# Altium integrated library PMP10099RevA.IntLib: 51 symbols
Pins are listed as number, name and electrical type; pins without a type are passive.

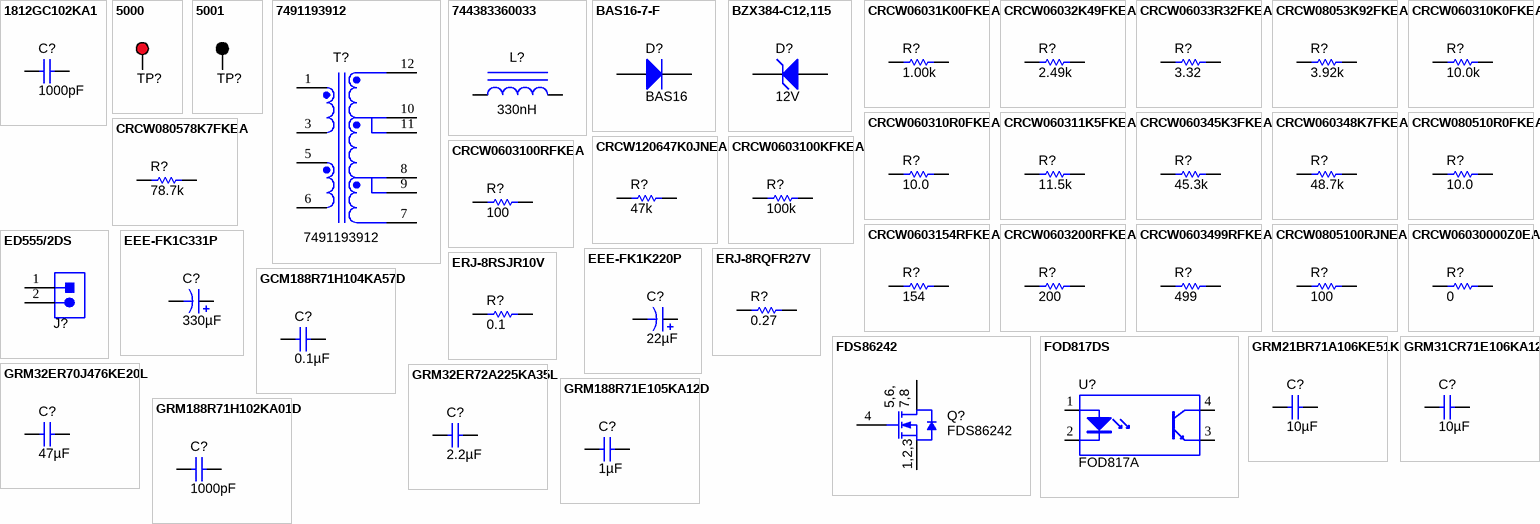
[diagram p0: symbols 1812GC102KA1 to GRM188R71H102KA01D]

## 1812GC102KA1
designator C?  ValueDisplayed: 1000pF  (hidden comment: 1812GC102KA1)
CAP, CERM, 1000 pF, 2000 V, +/- 10%, X7R, 1812; Manufacturer: AVX; Polarized: N; CompType: Capacitor; Value: 1000pF; U/M: EA; Cap_F: 0.000000001; Tolerance_%: 10; Value1: Unknown; VDC_V: 2000; Value2: 2000V; TaMin_C: -55; TaMax_C: 125; Cap_Case: 1812
signal-integrity model Cap
simulation model Cap
footprint 1812
footprint 1812M
footprint 1812L
footprint 1812_HV
pins: 1, 2

## 5000
designator TP?  (value not drawn)
Test Point, Miniature, Red, TH; Manufacturer: Keystone; CompType: Test Point Loop; U/M: EA
footprint Keystone5000
pins: 1

## 5001
designator TP?  (value not drawn)
Test Point, Miniature, Black, TH; Manufacturer: Keystone; CompType: Test Point Loop; U/M: EA
footprint Keystone5001
pins: 1

## 7491193912
designator T?
Transformer, 120 uH, SMT; Manufacturer: Wurth Elektronik eiSos; SymbolCreator: Altium; DCR_Ohm: 0.22; Value: 120 uH; LeakageL: 1.5 uH; U/M: EA
footprint WURTH_7491193912
pins: 1, 3, 5, 6, 7, 8, 9, 10, 11, 12

## 744383360033
designator L?, comment 330nH
Inductor, 330 nH, 5.5 A, 0.014 ohm, SMD; PartNumber: 744383360033; Manufacturer: Wurth Elektronik eiSos; Ind_H: 330.0E-9; Imax_A: 5.5; Irms: 5.5A @ 40C rise; Isat: 8.3A @ 20% inductance drop; DCR_ohm: 0.014; Value2: 5.5A
signal-integrity model Inductor
simulation model Inductor
footprint WE-MAPI_3020
pins: 1, 2

## BAS16-7-F
designator D?, comment BAS16
Diode, Ultrafast, 75 V, 0.3 A, SOT-23; PartNumber: BAS16-7-F; Manufacturer: Diodes Inc.; U/M: EA; Vf_V: 1.125; Value: 75V; Value1: 0.3A; Value2: 1.125V; Io_A: 0.3; Vr_V: 75
signal-integrity model Model Name (Model Description)
simulation model DI_MMBD4148
footprint SOT-23
footprint SOT-23M
footprint SOT-23L
pins: 1 A, 3 K

## BZX384-C12,115
designator D?  value 12V  (hidden comment: BZX384-C12,115)
Diode, Zener, 12 V, 300 mW, SOD-323; Manufacturer: NXP Semiconductor; SymbolCreator: a0412235; U/M: EA; Power_W: 0.3; Vz_V: 12; Value1: 0.3W; RJA_CperW: 415
signal-integrity model Diode
footprint sod-323
pins: 1 K, 2 A

## CRCW06031K00FKEA
designator R?  ValueDisplayed: 1.00k  (hidden comment: CRCW06031K00FKEA)
RES, 1.00 k, 1%, 0.1 W, 0603; Manufacturer: Vishay-Dale; CompType: Resistor; Value: 1.00k; Res_ohm: 1000; Value_Code: 1k00; Tolerance_%: 1; Power_W: 0.1; Value2: 0.1W; VDC_V: 75; TempCo: 100 ppm/C; EIA_Code: E96; U/M: EA
signal-integrity model Resistor
simulation model Resistor
footprint 0603
footprint 0603M
footprint 0603L
footprint 0603_HV
footprint 0603S
pins: 1, 2

## CRCW06032K49FKEA
designator R?  ValueDisplayed: 2.49k  (hidden comment: CRCW06032K49FKEA)
RES, 2.49 k, 1%, 0.1 W, 0603; Manufacturer: Vishay-Dale; CompType: Resistor; Value: 2.49k; Res_ohm: 2490; Value_Code: 2k49; Tolerance_%: 1; Power_W: 0.1; Value2: 0.1W; VDC_V: 75; TempCo: 100 ppm/C; EIA_Code: E96; U/M: EA
signal-integrity model Resistor
simulation model Resistor
footprint 0603
footprint 0603M
footprint 0603L
footprint 0603_HV
footprint 0603S
pins: 1, 2

## CRCW06033R32FKEA
designator R?  ValueDisplayed: 3.32  (hidden comment: CRCW06033R32FKEA)
RES, 3.32, 1%, 0.1 W, 0603; Manufacturer: Vishay-Dale; CompType: Resistor; Value: 3.32; Value_Code: 3R32; Tolerance_%: 1; Power_W: 0.1; Value2: 0.1W; VDC_V: 75; TempCo: 100 ppm/C; EIA_Code: E96; U/M: EA
signal-integrity model Resistor
simulation model Resistor
footprint 0603
footprint 0603M
footprint 0603L
footprint 0603_HV
footprint 0603S
pins: 1, 2

## CRCW08053K92FKEA
designator R?  value 3.92k  (hidden comment: CRCW08053K92FKEA)
RES, 3.92k ohm, 1%, 0.125W, 0805; Manufacturer: Vishay-Dale; CompType: Resistor; Res_ohm: 3920; Value_Code: 3k92; Tolerance_%: 1; Power_W: 0.125; VDC_V: 150; TempCo: 100 ppm/C; EIA_Code: E96; U/M: EA
signal-integrity model Resistor
simulation model Resistor
footprint 0805_HV
footprint 0805
footprint 0805M
footprint 0805L
pins: 1, 2

## CRCW060310K0FKEA
designator R?  ValueDisplayed: 10.0k  (hidden comment: CRCW060310K0FKEA)
RES, 10.0 k, 1%, 0.1 W, 0603; Manufacturer: Vishay-Dale; CompType: Resistor; Value: 10.0k; Res_ohm: 10000; Value_Code: 10k0; Tolerance_%: 1; Power_W: 0.1; Value2: 0.1W; VDC_V: 75; TempCo: 100 ppm/C; EIA_Code: E96; U/M: EA
signal-integrity model Resistor
simulation model Resistor
footprint 0603
footprint 0603M
footprint 0603L
footprint 0603_HV
footprint 0603S
pins: 1, 2

## CRCW060310R0FKEA
designator R?  ValueDisplayed: 10.0  (hidden comment: CRCW060310R0FKEA)
RES, 10.0, 1%, 0.1 W, 0603; Manufacturer: Vishay-Dale; CompType: Resistor; Value: 10.0; Res_ohm: 10; Value_Code: 10R0; Tolerance_%: 1; Power_W: 0.1; Value2: 0.1W; VDC_V: 75; TempCo: 100 ppm/C; EIA_Code: E96; U/M: EA
signal-integrity model Resistor
simulation model Resistor
footprint 0603
footprint 0603M
footprint 0603L
footprint 0603_HV
footprint 0603S
pins: 1, 2

## CRCW060311K5FKEA
designator R?  ValueDisplayed: 11.5k  (hidden comment: CRCW060311K5FKEA)
RES, 11.5 k, 1%, 0.1 W, 0603; Manufacturer: Vishay-Dale; CompType: Resistor; Value: 11.5k; Res_ohm: 11500; Value_Code: 11k5; Tolerance_%: 1; Power_W: 0.1; Value2: 0.1W; VDC_V: 75; TempCo: 100 ppm/C; EIA_Code: E96; U/M: EA
signal-integrity model Resistor
simulation model Resistor
footprint 0603
footprint 0603M
footprint 0603L
footprint 0603_HV
footprint 0603S
pins: 1, 2

## CRCW060345K3FKEA
designator R?  ValueDisplayed: 45.3k  (hidden comment: CRCW060345K3FKEA)
RES, 45.3 k, 1%, 0.1 W, 0603; Manufacturer: Vishay-Dale; CompType: Resistor; Value: 45.3k; Res_ohm: 45300; Value_Code: 45k3; Tolerance_%: 1; Power_W: 0.1; Value2: 0.1W; VDC_V: 75; TempCo: 100 ppm/C; EIA_Code: E96; U/M: EA
signal-integrity model Resistor
simulation model Resistor
footprint 0603
footprint 0603M
footprint 0603L
footprint 0603_HV
footprint 0603S
pins: 1, 2

## CRCW060348K7FKEA
designator R?  ValueDisplayed: 48.7k  (hidden comment: CRCW060348K7FKEA)
RES, 48.7 k, 1%, 0.1 W, 0603; Manufacturer: Vishay-Dale; CompType: Resistor; Value: 48.7k; Res_ohm: 48700; Value_Code: 48k7; Tolerance_%: 1; Power_W: 0.1; Value2: 0.1W; VDC_V: 75; TempCo: 100 ppm/C; EIA_Code: E96; U/M: EA
signal-integrity model Resistor
simulation model Resistor
footprint 0603
footprint 0603M
footprint 0603L
footprint 0603_HV
footprint 0603S
pins: 1, 2

## CRCW080510R0FKEA
designator R?  value 10.0  (hidden comment: CRCW080510R0FKEA)
RES, 10.0 ohm, 1%, 0.125W, 0805; Manufacturer: Vishay-Dale; CompType: Resistor; Res_ohm: 10; Value_Code: 10R0; Tolerance_%: 1; Power_W: 0.125; VDC_V: 150; TempCo: 100 ppm/C; EIA_Code: E96; U/M: EA
signal-integrity model Resistor
simulation model Resistor
footprint 0805_HV
footprint 0805
footprint 0805M
footprint 0805L
pins: 1, 2

## CRCW080578K7FKEA
designator R?  value 78.7k  (hidden comment: CRCW080578K7FKEA)
RES, 78.7k ohm, 1%, 0.125W, 0805; Manufacturer: Vishay-Dale; CompType: Resistor; Res_ohm: 78700; Value_Code: 78k7; Tolerance_%: 1; Power_W: 0.125; VDC_V: 150; TempCo: 100 ppm/C; EIA_Code: E96; U/M: EA
signal-integrity model Resistor
simulation model Resistor
footprint 0805_HV
footprint 0805
footprint 0805M
footprint 0805L
pins: 1, 2

## CRCW120647K0JNEA
designator R?  ValueDisplayed: 47k  (hidden comment: CRCW120647K0JNEA)
RES, 47 k, 5%, 0.25 W, 1206; Manufacturer: Vishay-Dale; CompType: Resistor; Value: 47k; Res_ohm: 47000; Value_Code: 47k0; Tolerance_%: 5; Power_W: 0.25; Value2: 0.25W; VDC_V: 200; TempCo: 200 ppm/C; EIA_Code: E24; U/M: EA
signal-integrity model Resistor
simulation model Resistor
footprint 1206
footprint 1206M
footprint 1206L
pins: 1, 2

## CRCW0603100KFKEA
designator R?  ValueDisplayed: 100k  (hidden comment: CRCW0603100KFKEA)
RES, 100 k, 1%, 0.1 W, 0603; Manufacturer: Vishay-Dale; CompType: Resistor; Value: 100k; Res_ohm: 100000; Tolerance_%: 1; Power_W: 0.1; Value2: 0.1W; VDC_V: 75; TempCo: 100 ppm/C; EIA_Code: E96; U/M: EA
signal-integrity model Resistor
simulation model Resistor
footprint 0603
footprint 0603M
footprint 0603L
footprint 0603_HV
footprint 0603S
pins: 1, 2

## CRCW0603100RFKEA
designator R?  ValueDisplayed: 100  (hidden comment: CRCW0603100RFKEA)
RES, 100, 1%, 0.1 W, 0603; Manufacturer: Vishay-Dale; CompType: Resistor; Value: 100; Value_Code: 100R; Tolerance_%: 1; Power_W: 0.1; Value2: 0.1W; VDC_V: 75; TempCo: 100 ppm/C; EIA_Code: E96; U/M: EA
signal-integrity model Resistor
simulation model Resistor
footprint 0603
footprint 0603M
footprint 0603L
footprint 0603_HV
footprint 0603S
pins: 1, 2

## CRCW0603154RFKEA
designator R?  ValueDisplayed: 154  (hidden comment: CRCW0603154RFKEA)
RES, 154, 1%, 0.1 W, 0603; Manufacturer: Vishay-Dale; CompType: Resistor; Value: 154; Value_Code: 154R; Tolerance_%: 1; Power_W: 0.1; Value2: 0.1W; VDC_V: 75; TempCo: 100 ppm/C; EIA_Code: E96; U/M: EA
signal-integrity model Resistor
simulation model Resistor
footprint 0603
footprint 0603M
footprint 0603L
footprint 0603_HV
footprint 0603S
pins: 1, 2

## CRCW0603200RFKEA
designator R?  ValueDisplayed: 200  (hidden comment: CRCW0603200RFKEA)
RES, 200, 1%, 0.1 W, 0603; Manufacturer: Vishay-Dale; CompType: Resistor; Value: 200; Value_Code: 200R; Tolerance_%: 1; Power_W: 0.1; Value2: 0.1W; VDC_V: 75; TempCo: 100 ppm/C; EIA_Code: E96; U/M: EA
signal-integrity model Resistor
simulation model Resistor
footprint 0603
footprint 0603M
footprint 0603L
footprint 0603_HV
footprint 0603S
pins: 1, 2

## CRCW0603499RFKEA
designator R?  ValueDisplayed: 499  (hidden comment: CRCW0603499RFKEA)
RES, 499, 1%, 0.1 W, 0603; Manufacturer: Vishay-Dale; CompType: Resistor; Value: 499; Value_Code: 499R; Tolerance_%: 1; Power_W: 0.1; Value2: 0.1W; VDC_V: 75; TempCo: 100 ppm/C; EIA_Code: E96; U/M: EA
signal-integrity model Resistor
simulation model Resistor
footprint 0603
footprint 0603M
footprint 0603L
footprint 0603_HV
footprint 0603S
pins: 1, 2

## CRCW0805100RJNEA
designator R?  value 100  (hidden comment: CRCW0805100RJNEA)
RES, 100 ohm, 5%, 0.125W, 0805; Manufacturer: Vishay-Dale; CompType: Resistor; Value_Code: 100R; Tolerance_%: 5; Power_W: 0.125; VDC_V: 150; TempCo: 200 ppm/C; EIA_Code: E24; U/M: EA
signal-integrity model Resistor
simulation model Resistor
footprint 0805_HV
footprint 0805
footprint 0805M
footprint 0805L
pins: 1, 2

## CRCW06030000Z0EA
designator R?  ValueDisplayed: 0  (hidden comment: CRCW06030000Z0EA)
RES, 0, 5%, 0.1 W, 0603; Manufacturer: Vishay-Dale; CompType: Resistor; Value: 0; Value_Code: 0000; Tolerance_%: 5; Power_W: 0.1; Value2: 0.1W; VDC_V: 75; TempCo: 200 ppm/C; EIA_Code: E24; U/M: EA
signal-integrity model Resistor
simulation model Resistor
footprint 0603
footprint 0603M
footprint 0603L
footprint 0603_HV
footprint 0603S
pins: 1, 2

## ED555/2DS
designator J?  (value not drawn)
Terminal Block, 6A, 3.5mm Pitch, 2-Pos, TH; Manufacturer: On-Shore Technology; SymbolCreator: a0412235; CompType: Connector; U/M: EA
footprint TERM_BLK_ED555-2DS
pins: 1, 2
1 alternate drawing of the same symbol

## EEE-FK1C331P
designator C?  ValueDisplayed: 330µF  (hidden comment: EEE-FK1C331P)
CAP, AL, 330 µF, 16 V, +/- 20%, 0.16 ohm, SMD; Manufacturer: Panasonic; Polarized: Y; CompType: Capacitor; Value: 330uF; U/M: EA; Cap_F: 0.00033; Tolerance_%: 20; VDC_V: 16; Value2: 16V; ESR_ohm: 0.16; IRMS_A: 0.6; TaMin_C: -55; TaMax_C: 105; Cap_Case: F
signal-integrity model Cap
simulation model Cap
footprint SM_RADIAL_F
pins: 1 +, 2 -

## EEE-FK1K220P
designator C?  ValueDisplayed: 22µF  (hidden comment: EEE-FK1K220P)
CAP, AL, 22 µF, 80 V, +/- 20%, 1.3 ohm, SMD; Manufacturer: Panasonic; Polarized: Y; CompType: Capacitor; Value: 22uF; U/M: EA; Cap_F: 0.000022; Tolerance_%: 20; Value1: 1.3 ohm; VDC_V: 80; Value2: 80V; ESR_ohm: 1.3; IRMS_A: 0.13; TaMin_C: -55; TaMax_C: 105; Cap_Case: F
signal-integrity model Cap
simulation model Cap
footprint SM_RADIAL_F
pins: 1 +, 2 -

## ERJ-8RQFR27V
designator R?  ValueDisplayed: 0.27  (hidden comment: ERJ-8RQFR27V)
RES, 0.27, 1%, 0.25 W, 1206; Manufacturer: Panasonic; CompType: Resistor; Value: 0.27; Value_Code: R270; Tolerance_%: 1; Power_W: 0.25; Value2: 0.25W; TempCo: 250 ppm/C; EIA_Code: E96; U/M: EA
signal-integrity model Resistor
simulation model Resistor
footprint 1206
footprint 1206M
footprint 1206L
pins: 1, 2

## ERJ-8RSJR10V
designator R?  ValueDisplayed: 0.1  (hidden comment: ERJ-8RSJR10V)
RES, 0.1, 5%, 0.25 W, 1206; Manufacturer: Panasonic; CompType: Resistor; Value: 0.1; Value_Code: R100; Tolerance_%: 5; Power_W: 0.25; Value2: 0.25W; TempCo: 250 ppm/C; EIA_Code: E24; U/M: EA
signal-integrity model Resistor
simulation model Resistor
footprint 1206
footprint 1206M
footprint 1206L
pins: 1, 2

## FDS86242
designator Q?
MOSFET, N-CH, 150 V, 4.1 A, SOIC-8; Manufacturer: Fairchild Semiconductor; Alternate Manufacturer: None; U/M: EA; ChType: N; Value: 150V; VdsMax_V: 150; Value1: 0.067 ohm; Rdson45_ohm: 0.067; Value2: 13 nC; QgTyp_nC: 13; Vgs_V: 4; IdsMax_A: 4.1
footprint SOIC-8
footprint SOIC-8M
footprint SOIC-8L
pins: 1 S, 2 S, 3 S, 4 G, 5 D, 6 D, 7 D, 8 D

## FOD817DS
designator U?, comment FOD817A
Optocoupler, 5kV RMS, SMT; PartNumber: FOD817DS; Manufacturer: Fairchild Semiconductor; U/M: EA
footprint N04C
pins: 1 A, 2 K, 3 E, 4 C

## GCM188R71H104KA57D
designator C?  ValueDisplayed: 0.1µF  (hidden comment: GCM188R71H104KA57D)
CAP, CERM, 0.1 µF, 50 V, +/- 10%, X7R, 0603; Manufacturer: MuRata; Polarized: N; CompType: Capacitor; Value: 0.1uF; U/M: EA; Cap_F: 0.0000001; Tolerance_%: 10; ESR_ohm: 0.02; Value1: 0.02 ohm; VDC_V: 50; Value2: 50V; IRMS_A: 1.84; TaMin_C: -55; TaMax_C: 125; Cap_Case: 0603
signal-integrity model Cap
simulation model Cap
footprint 0603
footprint 0603M
footprint 0603L
footprint 0603_HV
footprint 0603S
pins: 1, 2

## GRM21BR71A106KE51K
designator C?  ValueDisplayed: 10µF  (hidden comment: GRM21BR71A106KE51K)
CAP, CERM, 10 µF, 10 V, +/- 10%, X7R, 0805_140; Manufacturer: MuRata; Polarized: N; CompType: Capacitor; Value: 10uF; U/M: EA; Cap_F: 0.00001; Tolerance_%: 10; Value1: Unknown; Value2: 10V; TaMin_C: -55; TaMax_C: 125; Cap_Case: 0805
signal-integrity model Cap
simulation model Cap
footprint 0805_140
pins: 1, 2

## GRM31CR71E106KA12L
designator C?  ValueDisplayed: 10µF  (hidden comment: GRM31CR71E106KA12L)
CAP, CERM, 10 µF, 25 V, +/- 10%, X7R, 1206; Manufacturer: MuRata; Polarized: N; CompType: Capacitor; Value: 10uF; U/M: EA; Cap_F: 0.00001; Tolerance_%: 10; Value1: Unknown; VDC_V: 25; Value2: 25V; TaMin_C: -55; TaMax_C: 125; Cap_Case: 2220
signal-integrity model Cap
simulation model Cap
footprint 1206
footprint 1206M
footprint 1206L
pins: 1, 2

## GRM32ER70J476KE20L
designator C?  ValueDisplayed: 47µF  (hidden comment: GRM32ER70J476KE20L)
CAP, CERM, 47 µF, 6.3 V, +/- 10%, X7R, 1210; Manufacturer: MuRata; Polarized: N; CompType: Capacitor; Value: 47uF; U/M: EA; Cap_F: 0.000047; Tolerance_%: 10; Value1: Unknown; VDC_V: 6.3; Value2: 6.3V; TaMin_C: -55; TaMax_C: 125; Cap_Case: 1210
signal-integrity model Cap
simulation model Cap
footprint 1210
footprint 1210M
footprint 1210L
pins: 1, 2

## GRM32ER72A225KA35L
designator C?  ValueDisplayed: 2.2µF  (hidden comment: GRM32ER72A225KA35L)
CAP, CERM, 2.2 µF, 100 V, +/- 10%, X7R, 1210; Manufacturer: MuRata; Polarized: N; CompType: Capacitor; Value: 2.2uF; U/M: EA; Cap_F: 0.0000022; Tolerance_%: 10; ESR_ohm: 0.007; Value1: 0.007 ohm; VDC_V: 100; Value2: 100V; IRMS_A: 4.4; TaMin_C: -55; TaMax_C: 125; Cap_Case: 1210
signal-integrity model Cap
simulation model Cap
footprint 1210
footprint 1210M
footprint 1210L
pins: 1, 2

## GRM188R71E105KA12D
designator C?  ValueDisplayed: 1µF  (hidden comment: GRM188R71E105KA12D)
CAP, CERM, 1 µF, 25 V, +/- 10%, X7R, 0603; Manufacturer: MuRata; Polarized: N; CompType: Capacitor; Value: 1uF; U/M: EA; Cap_F: 0.000001; Tolerance_%: 10; Value1: Unknown; VDC_V: 25; Value2: 25V; TaMin_C: -55; TaMax_C: 125; Cap_Case: 0603
signal-integrity model Cap
simulation model Cap
footprint 0603
footprint 0603M
footprint 0603L
footprint 0603_HV
footprint 0603S
pins: 1, 2

## GRM188R71H102KA01D
designator C?  ValueDisplayed: 1000pF  (hidden comment: GRM188R71H102KA01D)
CAP, CERM, 1000 pF, 50 V, +/- 10%, X7R, 0603; Manufacturer: MuRata; Polarized: N; CompType: Capacitor; Value: 1000pF; U/M: EA; Cap_F: 0.000000001; Tolerance_%: 10; Value1: Unknown; VDC_V: 50; Value2: 50V; TaMin_C: -55; TaMax_C: 125; Cap_Case: 0603
signal-integrity model Cap
simulation model Cap
footprint 0603
footprint 0603M
footprint 0603L
footprint 0603_HV
footprint 0603S
pins: 1, 2

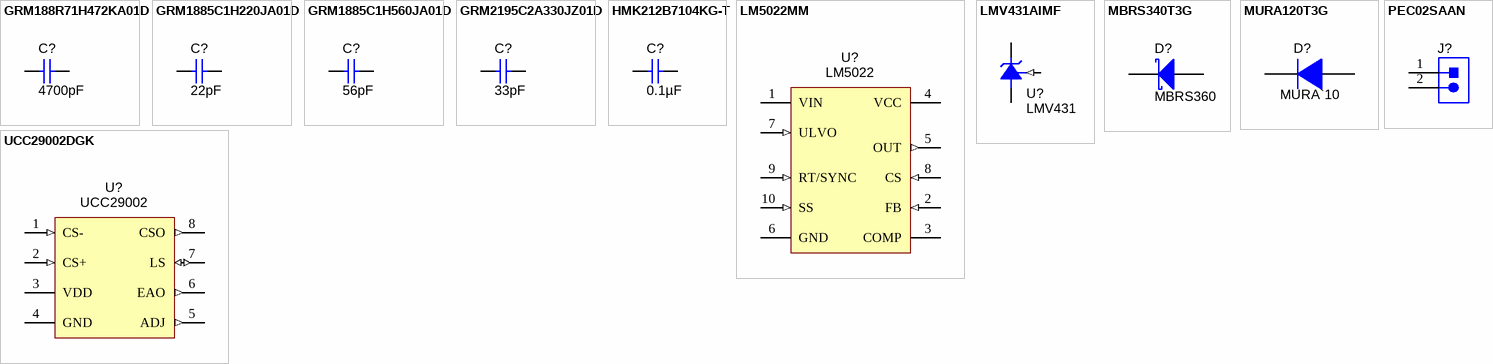
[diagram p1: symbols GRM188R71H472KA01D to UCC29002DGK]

## GRM188R71H472KA01D
designator C?  ValueDisplayed: 4700pF  (hidden comment: GRM188R71H472KA01D)
CAP, CERM, 4700 pF, 50 V, +/- 10%, X7R, 0603; Manufacturer: MuRata; Polarized: N; CompType: Capacitor; Value: 4700pF; U/M: EA; Cap_F: 0.0000000047; Tolerance_%: 10; Value1: Unknown; VDC_V: 50; Value2: 50V; TaMin_C: -55; TaMax_C: 125; Cap_Case: 0603
signal-integrity model Cap
simulation model Cap
footprint 0603
footprint 0603M
footprint 0603L
footprint 0603_HV
footprint 0603S
pins: 1, 2

## GRM1885C1H220JA01D
designator C?  ValueDisplayed: 22pF  (hidden comment: GRM1885C1H220JA01D)
CAP, CERM, 22 pF, 50 V, +/- 5%, C0G/NP0, 0603; Manufacturer: MuRata; Polarized: N; CompType: Capacitor; Value: 22pF; U/M: EA; Cap_F: 0.000000000022; Tolerance_%: 5; Value1: Unknown; VDC_V: 50; Value2: 50V; TaMin_C: -55; TaMax_C: 125; Cap_Case: 0603
signal-integrity model Cap
simulation model Cap
footprint 0603
footprint 0603M
footprint 0603L
footprint 0603_HV
footprint 0603S
pins: 1, 2

## GRM1885C1H560JA01D
designator C?  ValueDisplayed: 56pF  (hidden comment: GRM1885C1H560JA01D)
CAP, CERM, 56 pF, 50 V, +/- 5%, C0G/NP0, 0603; Manufacturer: MuRata; Polarized: N; CompType: Capacitor; Value: 56pF; U/M: EA; Cap_F: 0.000000000056; Tolerance_%: 5; Value1: Unknown; VDC_V: 50; Value2: 50V; TaMin_C: -55; TaMax_C: 125; Cap_Case: 0603
signal-integrity model Cap
simulation model Cap
footprint 0603
footprint 0603M
footprint 0603L
footprint 0603_HV
footprint 0603S
pins: 1, 2

## GRM2195C2A330JZ01D
designator C?  ValueDisplayed: 33pF  (hidden comment: GRM2195C2A330JZ01D)
CAP, CERM, 33 pF, 100 V, +/- 5%, C0G/NP0, 0805; Manufacturer: MuRata; Polarized: N; CompType: Capacitor; Value: 33pF; U/M: EA; Cap_F: 0.000000000033; Tolerance_%: 5; Value1: Unknown; VDC_V: 100; Value2: 100V; TaMin_C: -55; TaMax_C: 125; Cap_Case: 0805
signal-integrity model Cap
simulation model Cap
footprint 0805_HV
footprint 0805
footprint 0805M
footprint 0805L
pins: 1, 2

## HMK212B7104KG-T
designator C?  ValueDisplayed: 0.1µF  (hidden comment: HMK212B7104KG-T)
CAP, CERM, 0.1 µF, 100 V, +/- 10%, X7R, 0805; Manufacturer: Taiyo Yuden; Polarized: N; CompType: Capacitor; Value: 0.1uF; U/M: EA; Cap_F: 0.0000001; Tolerance_%: 10; Value1: Unknown; VDC_V: 100; Value2: 100V; TaMin_C: -55; TaMax_C: 125; Cap_Case: 0805
signal-integrity model Cap
simulation model Cap
footprint 0805_HV
footprint 0805
footprint 0805M
footprint 0805L
pins: 1, 2

## LM5022MM
designator U?, comment LM5022
60V Low Side Controller for Boost and SEPIC, 10-pin MSOP; PartNumber: LM5022MM; Manufacturer: Texas Instruments; PackageTopMarking: ZXTT*5022; PowerWise: Y; CompType: Switcher
footprint MUB10A_N (TSSOP, 10-Leads, Body 3x3mm, Pitch 0.5mm, IPC Medium Density)
footprint MUB10A_L (TSSOP, 10-Leads, Body 3x3mm, Pitch 0.5mm, IPC High Density)
footprint MUB10A_M (TSSOP, 10-Leads, Body 3x3mm, Pitch 0.5mm, IPC Low Density)
pins: 1 VIN (power), 2 FB (in), 3 COMP, 4 VCC (power), 5 OUT (out), 6 GND (power), 7 ULVO (in), 8 CS (in), 9 RT/SYNC (in), 10 SS (in)

## LMV431AIMF
designator U?, comment LMV431
Low-Voltage (1.24V) Adjustable Precision Shunt Regulator, 3-pin SOT-23; PartNumber: LMV431AIMF; Manufacturer: Texas Instruments; PackageTopMarking: RLA*XTT; PowerWise: N; CompType: MiscPower
footprint MF03A_N (SOT23, 3-Leads, Body 2.9x1.3mm, Pitch 0.95mm, Lead Span 2.4mm, IPC Medium Density)
footprint MF03A_L (SOT23, 3-Leads, Body 2.9x1.3mm, Pitch 0.95mm, Lead Span 2.4mm, IPC High Density)
footprint MF03A_M (SOT23, 3-Leads, Body 2.9x1.3mm, Pitch 0.95mm, Lead Span 2.4mm, IPC Low Density)
pins: 1 REF (in), 2 K, 3 A

## MBRS340T3G
designator D?, comment MBRS360
Diode, Schottky, 60 V, 3 A, SMC; PartNumber: MBRS360T3G; Manufacturer: ON Semiconductor; U/M: EA; Vf_V: 0.525; Value: 60V; Value1: 3A; Value2: 0.525V; Io_A: 3; Vr_V: 60; TJmax_C: 125; RJC_CperW: 11
signal-integrity model Diode
simulation model mbrs340t3
footprint SMC
pins: 1 K, 2 A

## MURA120T3G
designator D?, comment MURA`10
Diode, Ultrafast, 200 V, 1 A, SMA; PartNumber: MURA120T3G; Manufacturer: ON Semiconductor; U/M: EA; Vf_V: 0.0875; Value: 200V; Value1: 1A; Value2: 0.0875V; Io_A: 1; Vr_V: 200; TJmax_C: 175
signal-integrity model Diode
footprint SMA
pins: 1 K, 2 A

## PEC02SAAN
designator J?  (value not drawn)
Header, 100mil, 2x1, Tin, TH; Manufacturer: Sullins Connector Solutions; SymbolCreator: a0412235; U/M: EA
footprint CONN_PEC02SAAN
pins: 1, 2
1 alternate drawing of the same symbol

## UCC29002DGK
designator U?, comment UCC29002
ADVANCED 8-PIN LOAD SHARE CONTROLLER, DGK0008A; PartNumber: UCC29002DGK; Alternate Manufacturer: None; Manufacturer: Texas Instruments; SymbolCreator: a0411947; CompType: IC; U/M: EA
footprint DGK0008A_N
footprint DGK0008A_M
footprint DGK0008A_L
pins: 1 CS- (in), 2 CS+ (in), 3 VDD (power), 4 GND (power), 5 ADJ (out), 6 EAO (out), 7 LS (io), 8 CSO (out)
